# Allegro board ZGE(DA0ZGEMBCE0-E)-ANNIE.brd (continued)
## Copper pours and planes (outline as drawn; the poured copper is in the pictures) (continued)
S2 on TOP (solid shape): 249.07,33.95 249.07,32.25 249.12,32.2 249.12,31.97 249.09,31.97 249.09,31.26 249.09,31.23 248.91,31.23 248.89,31.26 248.89,31.26 248.89,31.97 248.86,31.97 248.86,32.05 248.74,32.17 245.54,32.17 245.43,32.27 245.43,32.43 245.49,32.48 245.49,32.47 246.2,32.47 246.2,32.5 246.37,32.5 246.42,32.55 246.42,33.77 246.35,33.85 246.2,33.85 246.2,33.87 245.49,33.87 245.46,33.9 245.46,34.05 245.49,34.08 245.49,34.07 246.2,34.07 246.2,34.1 248.91,34.1
S2 on BOTTOM (solid shape): 249.07,33.95 249.07,32.33 248.91,32.17 246.55,32.17 246.42,32.3 246.42,33.95 246.58,34.1 248.91,34.1
S_SPKR+ on TOP (solid shape): 20.82,19.4 20.82,18.13 20.67,17.97 19.98,17.97 19.5,17.49 19.5,16.58 18.86,15.94 16.53,15.94 16.35,16.12 16.35,16.73 16.66,17.03 17.35,17.03 17.4,16.98 18.49,16.98 19.42,17.92 19.42,18.25 19.54,18.37 19.54,19.26 19.75,19.47 20.75,19.47
S_SPKR- on TOP (solid shape): 18.64,15.49 18.64,14.55 18.36,14.27 16.58,14.27 16.41,14.43 16.41,15.33 16.68,15.6 18.53,15.6
S_SPKR- on BOTTOM (solid shape): 20.14,19.47 20.14,15.08 19.91,14.85 19.24,14.85 18.5,14.11 17.58,14.11 17.25,14.44 17.25,15.89 17.88,16.52 18.32,16.52 19.07,17.26 19.07,17.28 19.08,17.3 19.17,17.38 19.17,19.57 19.19,19.61 19.22,19.63 19.98,19.63
TBTA_CC1 on TOP (solid shape): 291.8,41.81 292.68,41.81 292.71,41.8 292.73,41.76 292.73,41.54 291.8,41.54 291.8,41.51 291.71,41.42 291.28,41.42 291.26,41.41 291.11,41.31 291.01,41.16 291.01,41.15 290.72,40.85 290.36,40.85 290.33,40.86 290.3,40.87 290.22,40.87 290.18,40.91 290.01,40.91 289.34,40.91 289.25,41 289.22,41.03 289.19,41.07 289.17,41.1 289.17,41.44 289.28,41.55 289.66,41.55 289.68,41.54 289.69,41.52 289.82,41.37 290.01,41.32 290.18,41.36 290.31,41.48 290.32,41.49 290.37,41.52 290.43,41.49 290.54,41.46 290.64,41.45 290.98,41.56 291.19,41.85 291.19,41.86 291.22,41.88 291.65,41.88 291.67,41.9 291.8,41.9
TBTA_CC2 on TOP (solid shape): 290.92,46.27 290.92,45.66 290.91,45.61 290.91,45.52 290.9,45.51 290.8,45.41 290.44,45.41 290.32,45.53 290.32,45.76 290.15,45.93 289.72,45.93 289.38,45.58 289.07,45.58 288.92,45.74 288.92,46.07 289.36,46.51 290.68,46.51
TBTA_VBUS_L on TOP (solid shape): 253.36,31.77 253.37,31.74 253.35,31.67 253.35,31.61 253.36,31.5 253.41,31.4 253.41,30.67 253.16,30.42 252.22,30.42 252.01,30.62 252.01,30.8 251.66,31.16 251.38,31.16 251.29,31.24 251.29,31.98 251.31,32.02 251.34,32.03 252.91,32.03 252.95,32.07 253.05,32.07
TBTA_VBUS_L on BOTTOM (solid shape): 287.17,48.99 287.17,47.11 286.78,46.73 283.43,46.73 283.3,46.85 283.3,48.81 283.81,49.32 286.84,49.32
TBTA_VBUS_L on IN2 (solid shape): outline of 1577 points within 284.4,39.47 294.23,48.63
TBTA_VBUS_L on SVCC1 (solid shape): outline of 800 points within 251.28,27.98 295.42,50.08
TPM_VDD on BOTTOM (solid shape): 242.54,19.17 242.89,19.17 243,19.07 243,18.38 242.87,18.25 241.96,18.25 241.74,18.03 241.24,18.03 241.14,17.92 241.13,17.88 241.09,17.87 241.08,17.87 241.08,16.87 241.04,16.83 240.82,16.83 240.79,16.85 240.77,16.88 240.77,17.87 240.76,17.87 240.72,17.88 240.71,17.92 240.71,18.23 240.89,18.41 240.9,18.41 240.95,18.44 240.97,18.48 240.98,18.5 241.01,18.53 241.01,18.79 241.34,19.12 241.75,19.12 241.98,19.35 242.36,19.35
TPM_VDD on BOTTOM (solid shape): 234.24,15.85 234.27,15.85 234.29,15.83 234.63,15.62 234.98,15.83 235,15.85 235.02,15.85 235.26,15.85 236.38,14.73 236.41,14.66 236.39,14.59 236.3,14.46 236.28,14.32 236.39,14.04 236.67,13.92 236.73,13.93 236.81,13.9 236.85,13.83 236.85,12.84 237,12.69 238.52,12.69 238.58,12.64 238.58,11.68 238.6,11.66 238.6,11.6 238.83,11.37 239.57,11.37 239.74,11.19 239.74,10.53 239.57,10.35 237.99,10.35 237.36,9.72 236.24,9.72 236.19,9.77 236.19,11.83 235.3,12.72 235.3,13.28 233.59,14.98 233.59,15.03 233.56,15.18 233.47,15.31 233.47,15.62 233.7,15.85
TPM_VDD on IN1 (solid shape): outline of 116 points within 233.37,14.88 242.52,18.65
USB3_RT_0V9 on TOP (solid shape): 270.42,36.05 270.42,36.03 270.46,35.9 270.55,35.78 270.55,35.76 270.55,34.89 270.44,34.77 270.42,34.77 270.24,34.67 270.14,34.49 270.14,34.47 269.92,34.26 269.92,33.97 269.89,33.88 269.88,33.8 269.89,33.72 269.92,33.63 269.92,33.52 269.79,33.39 268.95,33.39 268.88,33.47 268.88,36.08 269.06,36.26 270.2,36.26
USB3_RT_0V9 on TOP (solid shape): 269.53,30.49 269.53,28.41 269.52,28.38 269.48,28.36 268.76,28.36 268.5,28.52 268.2,28.57 268.12,28.57 268.04,28.56 268.02,28.56 268,28.56 267.9,28.61 267.79,28.63 267.67,28.61 267.57,28.56 267.55,28.56 267.53,28.56 267.44,28.57 267.35,28.57 267.1,28.53 266.87,28.42 266.86,28.41 266.82,28.41 266.74,28.49 266.74,29.4 266.85,29.51 267.68,29.51 267.99,29.81 267.99,30.6 268.16,30.77 268.17,30.77 268.28,30.81 268.37,30.88 269.14,30.88
USB3_RT_0V9 on BOTTOM (solid shape): 269.44,30.83 269.44,29.86 269.21,29.63 267.68,29.63 267.58,29.73 267.58,30.35 267.99,30.76 268.02,30.77 268.09,30.76 268.27,30.81 268.43,30.95 268.46,30.95 269.31,30.95
USB3_RT_0V9 on BOTTOM (solid shape): 270.42,36.22 270.43,36.19 270.42,36.13 270.41,36.08 270.45,35.93 270.55,35.78 270.55,35.76 270.55,34.89 270.48,34.82 270.46,34.81 270.33,34.78 270.23,34.71 269.03,34.71 268.88,34.87 268.88,36.14 269.08,36.34 270.3,36.34
USB3_RT_0V9 on IN4 (solid shape): outline of 608 points within 261.89,30.39 270.73,37
USB3_RT_DCDC_GND on TOP (solid shape): 268.88,38.29 268.88,37.91 268.83,37.86 265.68,37.86 265.58,37.96 265.58,38.29 265.8,38.52 268.65,38.52
USB3_RT_DCDC_GND on BOTTOM (solid shape): 265.33,34.83 265.33,34.57 265.65,34.26 265.65,33.93 265.55,33.82 265.19,33.82 264.94,34.08 263.85,34.08 263.75,34.18 263.75,34.94 263.87,35.07 265.09,35.07
USB3_RT_DCDC_GND on BOTTOM (solid shape): 268.88,38.29 268.88,36.85 268.37,36.34 268.37,34.61 268.22,34.46 268.01,34.46 267.8,34.67 267.8,34.8 267.61,34.99 267.61,36.08 267.91,36.39 267.91,37.05 267.63,37.33 266.74,37.33 266.41,37 265.68,37 265.58,37.1 265.58,38.29 265.8,38.52 268.65,38.52
USB3_RT_DCDC_GND on SGND (solid shape): 268.88,38.29 268.88,36.85 268.44,36.42 268.39,36.33 268.37,36.24 268.37,34.18 267.63,33.44 266.7,33.44 266.26,33.88 266.18,33.93 266.08,33.95 265.95,33.91 265.86,33.81 265.21,33.81 264.98,34.04 264.95,34.06 264.92,34.07 263.78,34.07 263.73,34.11 263.73,34.98 263.83,35.08 264.76,35.08 264.8,35.09 264.83,35.11 265.32,35.6 265.5,35.68 265.58,35.86 265.58,38.29 265.81,38.52 268.65,38.52
USB3_RT_DCDC_GND on IN1 (solid shape): outline of 95 points within 263.75,33.44 268.88,38.52
USB3_RT_DCDC_GND on SGND3 (solid shape): 268.88,38.29 268.88,36.85 268.44,36.42 268.39,36.33 268.37,36.24 268.37,34.18 267.63,33.44 266.7,33.44 266.26,33.88 266.18,33.93 266.08,33.95 265.95,33.91 265.86,33.81 265.21,33.81 264.98,34.04 264.95,34.06 264.92,34.07 263.78,34.07 263.73,34.11 263.73,34.98 263.83,35.08 264.76,35.08 264.8,35.09 264.83,35.11 265.32,35.6 265.5,35.68 265.58,35.86 265.58,38.29 265.81,38.52 268.65,38.52
USB3_RT_VIN on TOP (solid shape): 268.88,37.58 268.88,37 268.7,36.82 267.89,36.82 267.53,36.47 266.77,36.47 266.36,36.06 266.36,35.65 265.55,34.84 264.76,34.84 264.73,34.87 263.8,34.87 263.76,34.88 263.75,34.92 263.75,34.99 263.82,35.07 264.81,35.07 265.32,35.58 265.42,35.58 265.58,35.73 265.58,37.51 265.78,37.71 268.75,37.71
USB3_RT_VIN on BOTTOM (solid shape): 267.73,36.92 267.73,36.44 267.43,36.14 267.43,34.97 267.66,34.74 267.66,33.57 267.56,33.47 266.69,33.47 265.6,34.56 265.6,36.57 265.86,36.82 266.44,36.82 266.74,37.13 267.53,37.13
USB3_RT_VX on TOP (solid shape): 267.73,36.14 267.73,34.84 267.72,34.74 267.73,34.64 267.73,33.54 267.63,33.44 266.69,33.44 266.19,33.95 265.88,33.95 265.61,34.22 265.61,34.23 265.55,34.3 265.47,34.36 265.47,34.37 265.42,34.41 265.28,34.41 264.79,34.41 264.75,34.42 264.73,34.46 264.73,34.47 263.77,34.47 263.74,34.48 263.72,34.52 263.72,34.62 263.74,34.66 263.77,34.67 264.73,34.67 264.73,34.68 264.76,34.71 265.7,34.71 266.57,35.58 266.57,35.93 266.85,36.21 267.66,36.21
USB3O2_MUX_AVDD33 on TOP (solid shape): 277.8,30.88 277.83,30.87 278.15,30.53 278.58,30.41 278.81,30.41 278.95,30.27 279.49,30.27 279.53,30.26 279.55,30.22 279.55,28.92 279.52,28.9 279.52,27.96 279.04,27.47 278.02,27.47 277.67,27.83 277.67,28.56 277.68,28.59 277.94,28.74 278.04,29 277.99,29.18 277.86,29.34 277.85,29.36 277.85,29.57 277.67,29.75 277.67,29.76 277.58,29.85 277.58,29.85 277.58,30.84 277.62,30.88
USB3O2_MUX_AVDD33 on IN4 (solid shape): 278.76,30.53 278.76,29.4 278.45,29.1 277.87,29.1 276.93,30.04 271.82,30.04 271.62,30.24 271.62,31.03 271.94,31.35 277.95,31.35
USB_CC1 on TOP (solid shape): 286.6,36.82 287.73,36.82 288.23,36.31 288.23,35.98 288.16,35.91 287.74,35.91 287.59,36.06 287.59,36.07 287.55,36.16 287.46,36.2 287.12,36.19 286.61,36.19 286.47,36.06 286.31,36.06 286.19,36.18 285.95,36.18 285.95,36.19 285.95,36.67 286.12,36.85 286.58,36.85
USB_CC2 on TOP (solid shape): 286.53,38.68 286.54,38.66 286.54,38.64 286.52,38.56 286.52,38.5 286.55,38.34 286.64,38.21 286.66,38.17 286.66,37.86 286.96,37.56 287,37.56 287.05,37.52 287.11,37.5 287.14,37.49 287.18,37.49 287.26,37.48 287.29,37.47 287.66,37.47 287.74,37.56 288.16,37.56 288.61,37.1 288.61,36.8 288.49,36.67 288.18,36.67 287.92,36.94 287.84,36.94 287.83,36.95 286.66,36.95 285.95,37.66 285.95,38.04 285.69,38.29 285.69,38.57 285.97,38.85 286.35,38.85
USBC_VBUS on TOP (solid shape): 108.67,144.04 109.29,144.04 109.57,144.31 112.85,144.31 113.14,144.03 113.14,141.4 112.25,140.5 108.13,140.5 107.57,139.95 105.75,139.95 105.67,140.02 105.67,140.55 106.05,140.93 106.05,142.17 105.23,142.99 105.23,144.44 105.35,144.57 108.14,144.57
USBC_VBUS on BOTTOM (solid shape): outline of 230 points within 285.16,34.99 291.05,39.53
USBC_VBUS on SVCC (solid shape): outline of 2341 points within 110.51,24.45 294.28,156.02
USBC_VBUS on IN3 (solid shape): outline of 1380 points within 287.27,24.5 297.2,38.32
VA on TOP (solid shape): 120.26,167.53 120.26,166.67 120.87,166.06 122.24,166.06 123.21,167.02 123.21,167.91 123.39,168.09 125.49,168.09 125.82,167.76 125.82,166.49 125.32,165.98 125.32,163.72 125.72,163.31 126.61,163.31 127.45,162.47 127.45,159.38 126.87,158.79 126.87,158 126.74,157.88 125.98,157.88 124.89,158.97 121.18,158.97 120.9,158.69 120.9,157.98 120.54,157.62 119.96,157.62 119.73,157.85 119.73,163.26 119.28,163.71 117.93,163.71 117.47,164.16 117.47,167.83 117.85,168.22 119.58,168.22
VA on BOTTOM (solid shape): 95.41,52.61 95.41,52.47 95.41,52.41 95.44,52.35 95.45,52.33 95.45,51.65 95.27,51.48 95.04,51.48 94.86,51.65 94.86,51.81 94.61,52.06 94.3,52.06 94.1,52.26 94.1,52.75 94.2,52.85 95.17,52.85
VA on BOTTOM (solid shape): 119.98,167.63 119.98,166.46 120.54,165.9 122.52,165.9 123.18,166.56 123.18,167.68 123.64,168.14 125.39,168.14 125.8,167.73 125.8,162.81 125.72,162.73 118.51,162.73 117.27,163.97 117.27,167.55 117.85,168.14 119.47,168.14
N18847325 on TOP (solid shape): 167.13,160.54 167.13,159.1 168.55,157.67 168.55,153.36 168.07,152.87 166.08,152.87 165.78,153.18 165.78,153.52 165.74,153.62 165.64,153.66 165.26,153.66 165.16,153.62 165.12,153.52 165.12,153.18 165.12,153.14 165.14,153.1 165.14,152.21 164.69,151.76 161.18,151.76 160.55,152.39 160.55,155.46 161.05,155.97 162.15,155.97 162.55,156.38 162.55,159.2 162.68,159.33 166.21,159.33 166.41,159.53 166.41,160.47 166.62,160.67 167,160.67
N18847325 on BOTTOM (solid shape): 167.56,158.36 167.56,156.4 167.48,156.33 166.52,156.33 166.31,156.53 166.31,158.36 166.54,158.59 167.33,158.59
N18869846 on BOTTOM (solid shape): 165.75,158.11 165.75,156.46 165.68,156.38 165.04,156.38 164.89,156.53 164.89,158.13 165.09,158.33 165.53,158.33
N18875415 on TOP (solid shape): 156.53,160.42 156.53,159.3 156.97,158.86 156.97,156.27 158.13,155.11 158.13,152.57 157.7,152.14 155.29,152.14 155.09,152.34 155.09,153.64 154.98,153.74 154.37,153.74 154.27,153.64 154.27,151.98 153.89,151.6 149.83,151.6 149.29,152.14 149.29,155.97 149.42,156.1 151.43,156.1 151.71,156.38 151.71,158.94 151.96,159.2 155.37,159.2 155.8,159.63 155.8,160.62 155.9,160.72 156.23,160.72
N18875415 on BOTTOM (solid shape): 156.71,158.28 156.71,156.63 156.58,156.51 155.72,156.51 155.44,156.79 155.44,158.36 155.59,158.51 156.48,158.51
N18875619 on BOTTOM (solid shape): 154.98,158.39 154.98,156.61 154.86,156.48 154.43,156.48 154.17,156.73 154.17,158.36 154.37,158.56 154.81,158.56
N18877670 on TOP (solid shape): 146.6,160.6 146.6,153.18 145.66,152.24 144.39,152.24 143.91,152.72 143.91,153.41 143.68,153.64 143.63,153.64 143.59,153.64 143.21,153.64 143.18,153.64 143.02,153.64 142.94,153.56 142.94,152.37 142.79,152.21 139.21,152.21 138.58,152.85 138.58,155.77 138.96,156.15 140.71,156.15 141.24,156.68 141.24,159.05 141.55,159.35 145.61,159.35 145.76,159.5 145.76,160.8 145.81,160.85 146.35,160.85
N18877670 on BOTTOM (solid shape): 146.12,158.33 146.12,156.76 145.99,156.63 145.18,156.63 144.98,156.84 144.98,158.33 145.21,158.56 145.89,158.56
N18877832 on BOTTOM (solid shape): 144.44,158.46 144.44,156.71 144.34,156.61 143.73,156.61 143.5,156.84 143.5,158.39 143.78,158.66 144.24,158.66
N18879722 on TOP (solid shape): 136.06,160.57 136.06,158.66 135.76,158.36 135.76,153.1 135.22,152.57 133.09,152.57 132.63,153.03 132.63,153.61 132.56,153.69 132,153.69 131.95,153.64 131.95,152.82 131.67,152.54 128.77,152.54 128.03,153.28 128.03,156.02 128.49,156.48 129.71,156.48 130.14,156.91 130.14,157.93 131.44,159.22 135.07,159.22 135.27,159.43 135.27,160.65 135.32,160.7 135.93,160.7
N18879722 on BOTTOM (solid shape): 135.32,158.18 135.32,156.86 135.22,156.76 134.44,156.76 134.28,156.91 134.28,158.11 134.51,158.33 135.17,158.33
N18879884 on BOTTOM (solid shape): 133.78,158.51 133.78,156.84 133.65,156.71 133.06,156.71 132.86,156.91 132.86,158.41 133.11,158.66 133.62,158.66
N18886117 on TOP (solid shape): 124.35,156.33 124.78,156.33 125.34,155.77 125.34,152.87 124.76,152.29 123.49,152.29 123.36,152.42 123.36,153.97 123.23,154.09 123.13,154.09 123.09,154.1 122.71,154.1 122.68,154.09 122.62,154.09 122.42,153.89 122.42,152.39 119.63,149.6 118.2,149.6 118.13,149.67 118.13,153.38 117.85,153.66 116.76,153.66 116.6,153.81 116.6,154.42 118,155.82 119.32,155.82 120.26,156.76 123.92,156.76
N18886117 on BOTTOM (solid shape): 120.01,154.42 120.01,153.03 119.93,152.95 119.32,152.95 119.22,153.05 119.22,154.42 119.35,154.55 119.88,154.55
N18886423 on BOTTOM (solid shape): 118.64,153.69 118.64,151.98 118.46,151.81 118,151.81 117.87,151.93 117.87,153.74 117.95,153.81 118.51,153.81
N19453152 on TOP (solid shape): 199.78,48.29 199.78,48.1 201.16,46.72 201.16,46.27 202.78,44.65 203.7,44.65 203.78,44.57 203.78,44.02 203.77,43.98 203.73,43.97 203.62,43.86 203.45,43.86 203.33,43.98 202.5,43.98 201.18,45.3 199.59,45.3 199.46,45.43 199.46,46.02 199.15,46.33 199.15,47.06 199.01,47.2 199.01,47.21 199.01,48.29 199.1,48.38 199.69,48.38
N20974305 on TOP (solid shape): 96.53,78.49 96.53,77.91 96.21,77.59 96.11,77.59 96.06,77.55 96.05,77.54 95.82,77.41 95.73,77.16 95.85,76.88 96.13,76.76 96.24,76.78 96.34,76.82 96.37,76.83 96.4,76.81 96.44,76.78 96.44,75.91 96.37,75.79 96.35,75.66 96.46,75.38 96.73,75.26 96.76,75.26 97,75.02 97,74.59 96.97,74.51 96.97,74.44 96.97,74.37 97,74.3 97,73.63 96.89,73.52 96.41,73.52 96.28,73.65 96.28,74.74 96.12,74.91 96.11,74.92 96.08,74.98 96.02,75.02 96.01,75.02 95.17,75.86 95.17,77.55 95.18,77.58 95.38,77.58 95.48,77.62 95.52,77.72 95.52,78.33 95.78,78.58 96.44,78.58
N21715610 on BOTTOM (solid shape): 74.54,29.22 74.65,29.19 74.76,29.18 74.83,29.2 74.9,29.23 77.25,29.23 77.32,29.2 77.35,29.12 77.35,29.12 77.46,28.84 77.74,28.73 77.79,28.73 77.87,28.74 77.89,28.72 78,28.62 78,28.33 78,27.01 77.99,27 77.86,27 77.82,27.01 77.81,27.05 77.81,27.72 77.61,27.72 77.61,27.05 77.59,27.01 77.56,27 77.2,27 76.93,27.27 76.93,27.55 76.7,27.78 74.97,27.78 74.72,27.52 74.72,27.2 74.71,27.16 74.47,27.01 74.38,26.76 74.44,26.56 74.59,26.42 74.64,26.34 74.61,26.25 74.5,26.12 74.47,25.95 74.5,25.78 74.61,25.65 74.65,25.57 74.62,25.49 74.08,24.95 73.35,24.95 73.17,25.13 73.17,26.43 73.2,26.51 73.28,26.54 73.3,26.53 73.58,26.65 73.69,26.93 73.59,27.19 73.34,27.32 73.2,27.35 73.17,27.42 73.17,28.77 73.63,29.23 74.53,29.23
N21715657 on BOTTOM (solid shape): outline of 266 points within 79.41,25.37 84.37,30.32
N21716560 on TOP (solid shape): 95.93,30.12 95.93,29.3 95.8,29.18 94.05,29.18 93.74,28.87 93.74,27.3 94.14,26.9 94.14,26.72 94.12,26.68 94.09,26.67 93.42,26.67 93.42,26.45 94.12,26.45 94.13,26.44 94.14,26.42 94.14,26.32 94.12,26.28 94.09,26.27 93.25,26.27 92.81,26.71 92.53,26.71 92.2,27.03 92.2,28.59 92.23,28.64 92.24,28.65 92.46,29 92.24,29.35 92.23,29.36 92.2,29.4 92.2,30.12 92.3,30.22 95.83,30.22
N21716605 on TOP (solid shape): 93.42,24.85 94.16,24.85 94.16,24.72 94.15,24.68 94.11,24.67 93.42,24.67 93.42,24.45 94.16,24.45 94.16,24.23 93.97,24.04 93.67,24.04 93.4,23.78 93.4,22.53 93.59,22.34 93.65,22.34 93.74,22.31 93.82,22.3 93.9,22.31 93.99,22.34 94.02,22.34 94.08,22.4 94.15,22.43 94.22,22.4 94.34,22.33 94.48,22.3 94.72,22.38 94.86,22.59 94.87,22.62 95.52,22.62 95.62,22.52 95.62,21.73 94.97,21.08 93.83,21.08 93.83,21.09 93.54,21.09 93.54,21.23 93.49,21.33 93.4,21.37 93.02,21.37 93,21.4 92.28,21.4 91.94,21.73 91.94,22.15 91.99,22.26 92.01,22.38 91.99,22.48 91.96,22.56 91.94,22.58 91.94,22.77 92.25,23.08 92.25,24.76 92.4,24.91 93.42,24.91
N23334321 on TOP (solid shape): 160.57,25.26 160.57,24.98 160.47,24.88 159.91,24.88 159.78,24.76 159.78,24.27 159.73,24.22 159.15,24.22 159.02,24.35 158.67,24.35 158.57,24.45 158.57,24.71 159.18,25.31 160.52,25.31
N25255301 on TOP (solid shape): 119.47,163.19 119.47,160.06 119.3,159.88 118.41,159.88 117.87,159.35 117.87,158.94 117.39,158.46 117.39,157.42 117.21,157.24 116.4,157.24 116.3,157.34 116.3,158.21 116.66,158.56 116.66,162.07 116.99,162.4 117.47,162.4 117.75,162.68 117.75,163.19 118.13,163.57 119.09,163.57
N25255306 on TOP (solid shape): 72.66,47.75 72.66,45.05 71.79,44.17 68.03,44.17 68.01,44.19 64.96,44.19 64.78,44.37 64.78,44.74 64.84,44.79 64.99,44.94 64.99,45.26 64.05,46.19 63.8,46.19 63.59,46.4 63.59,46.63 63.72,46.75 64.5,46.75 64.81,47.07 66.49,47.07 66.49,47.02 66.53,46.92 66.63,46.88 67.01,46.88 67.11,46.92 67.15,47.02 67.15,47.08 67.39,47.32 67.41,47.31 67.55,47.34 67.67,47.41 68.95,47.41 69.7,48.17 72.25,48.17
N25255314 on TOP (solid shape): 119.5,159.4 119.5,157.52 119.12,157.14 117.82,157.14 117.62,157.34 117.62,158.39 118.05,158.82 118.05,159.3 118.43,159.68 119.22,159.68
N25255423 on TOP (solid shape): 116.06,163.52 116.06,158.83 114.52,157.29 106.52,157.29 106.37,157.45 106.37,160.14 106.65,160.42 110.79,160.42 111.07,160.7 111.07,163.11 111.58,163.63 115.95,163.63
N33880211 on TOP (solid shape): 226.84,24.52 226.91,24.49 226.96,24.44 226.96,24.41 227.08,24.29 227.22,24.29 227.74,24.29 228.72,23.3 228.72,22.36 230.35,20.73 230.35,19.77 230.88,19.24 231.49,19.24 231.63,19.11 231.63,19.09 231.64,19.02 231.67,18.95 231.67,18.56 231.66,18.55 230.76,18.55 230.69,18.48 230.3,18.48 230.21,18.57 230.21,18.91 230.13,18.99 230.12,19 230.03,19.17 229.86,19.27 229.85,19.27 229.66,19.46 229.66,19.71 229.66,20.2 229.58,20.29 229.55,20.31 229.34,20.52 229.3,20.52 229.27,20.55 227.73,22.08 227.73,22.72 227.75,22.76 227.76,22.77 227.86,23.02 227.76,23.27 227.75,23.28 227.73,23.32 227.73,23.43 227.61,23.56 227.61,23.56 227.35,23.82 226.99,23.82 226.89,23.92 226.87,23.92 226.62,24.17 226.62,24.35 226.71,24.44 226.77,24.49
N36119386 on TOP (solid shape): 106.88,96.99 106.94,96.99 107.1,96.83 107.1,96.81 107.08,96.72 107.07,96.65 107.19,96.37 107.47,96.26 107.68,96.26 107.78,96.16 108.93,96.16 109.05,96.05 109.05,95.58 108.87,95.41 107.6,95.41 107.58,95.42 107.57,95.44 107.42,95.59 107.22,95.65 107.06,95.61 106.93,95.52 106.86,95.48 106.78,95.51 106.39,95.9 105.53,95.9 105.3,96.13 105.3,97.32 105.48,97.5 106.37,97.5
N37522596 on TOP (solid shape): 234.6,57.47 234.6,57.46 235.4,57.46 235.44,57.44 235.45,57.41 235.45,57.23 235.44,57.19 235.4,57.18 234.6,57.18 234.6,57.17 234.57,57.14 234.46,57.14 234.08,56.76 234.08,56.67 233.94,56.53 233.94,55.37 234.08,55.23 234.08,54.55 233.68,54.15 229.65,54.15 229.13,54.68 229.13,56.84 229.79,57.5 234.57,57.5
N37522596 on BOTTOM (solid shape): 233.43,60.03 233.43,58.26 233.83,57.86 233.83,55.08 233.62,54.88 230.27,54.88 229.79,55.36 229.79,59.81 230.22,60.24 233.22,60.24
N37551639 on BOTTOM (solid shape): 228.59,59.88 228.59,58.26 228.26,57.93 227.58,57.93 227.53,57.94 227.49,57.94 227.44,57.94 227.39,57.93 225.39,57.93 225.27,58.06 225.27,58.72 225.34,58.78 225.77,58.78 226.16,59.18 226.16,60.1 226.26,60.19 228.29,60.19
N53212830 on TOP (solid shape): 36.87,35.31 36.87,34.85 36.87,34.83 36.77,34.69 36.75,34.54 36.75,33.95 36.75,33.89 36.77,33.82 36.77,33.7 36.62,33.56 36.15,33.56 36.06,33.65 34.46,33.65 34.42,33.67 34.38,33.72 34.33,33.76 34.32,33.78 34.31,33.8 34.31,34 34.39,34.08 34.42,34.09 34.45,34.09 34.83,34.09 34.86,34.09 34.9,34.11 35.79,34.11 36.32,34.63 36.32,35.35 36.39,35.41 36.77,35.41
N53212904 on TOP (solid shape): 31.79,36.29 31.79,36.04 31.77,35.97 31.7,35.94 31.33,35.57 31.66,35.16 31.67,35.16 31.72,35.11 31.72,34.84 31.62,34.74 30.98,34.74 30.78,34.54 30.78,34.15 30.51,33.88 30.51,32.87 30.47,32.83 30.34,32.83 30.31,32.87 30.31,33.97 30.32,33.99 30.33,34.01 30.5,34.28 30.39,34.58 30.38,34.59 30.37,34.61 30.37,35.25 31.11,35.98 31.11,36.29 31.24,36.41 31.67,36.41
N53217580 on TOP (solid shape): 12.14,22.77 12.14,22.5 11.97,22.33 11.96,22.31 11.38,21.74 11.18,21.74 10.53,21.09 10.53,20.36 10.3,20.12 9.62,20.12 9.6,20.13 9.58,20.14 9.54,20.18 9.54,21.08 9.52,21.1 9.51,21.12 9.5,21.14 9.5,21.22 9.58,21.3 10.19,21.3 10.76,21.87 10.76,22.19 10.99,22.41 10.99,22.66 11.12,22.79 12.12,22.79
N53217584 on TOP (solid shape): 10.46,26.76 10.46,26.41 11.47,25.39 11.96,25.39 12.16,25.19 12.16,24.83 12.12,24.79 11.13,24.79 11.13,24.78 11.04,24.78 10.71,25.11 10.71,25.37 10.28,25.8 9.47,25.8 9.26,26 9.26,26.99 9.37,27.09 10.13,27.09
N53218545 on TOP (solid shape): 22.35,17.62 22.35,16.62 22.26,16.53 20.15,16.53 20.03,16.65 20.03,17.41 20.34,17.72 22.24,17.72
N53218614 on TOP (solid shape): 24.62,16.11 24.65,16.03 24.61,15.95 24.25,15.13 24.82,14.44 24.82,14.09 24.69,13.96 23.26,13.96 23.13,14.08 23.13,15 23.24,15.11 23.33,15.11 23.34,15.1 23.43,15.07 23.53,15.05 23.81,15.17 23.93,15.45 23.92,15.52 23.9,15.6 23.9,16.13 23.9,16.27 23.9,16.27 24.45,16.27
N53276765 on TOP (solid shape): 42.97,104.97 43,104.96 43.02,104.94 43.08,104.86 43.16,104.81 43.17,104.81 43.71,104.27 43.71,104.26 43.77,104.17 43.86,104.11 43.87,104.11 44.13,103.85 44.13,102.81 44.11,102.77 44.07,102.76 43.2,102.76 43.07,102.89 43.07,103.01 43.55,103.5 43.55,103.75 43.33,103.98 42.64,103.98 42.32,104.3 42.32,104.5 42.44,104.61 42.72,104.61 42.92,104.82 42.92,104.94 42.95,104.97
N53276791 on TOP (solid shape): 45.07,107.9 45.08,107.88 45.08,107.86 45.08,107.14 45.04,107.06 44.95,107.05 44.89,107.06 44.84,107.06 44.53,106.76 44.84,106.45 44.89,106.46 44.95,106.47 45.04,106.46 45.08,106.38 45.08,105.57 45.08,105.55 45.07,105.54 44.74,105.21 44.33,105.21 44.01,104.9 43.91,104.9 43.52,105.29 43.52,105.92 43.41,106.03 43.09,106.03 42.95,105.89 42.44,105.89 42.36,105.81 42.18,105.81 42.08,105.91 42.08,106.29 43.93,108.14 44.82,108.14
N53276791 on BOTTOM (solid shape): 42.18,106.96 43,106.96 43.1,106.86 43.1,106.03 42.99,105.92 42.59,105.92 42.48,105.81 42.35,105.81 42.35,105.81 42.06,105.81 41.88,105.99 41.88,106.36 41.47,106.77 41.47,107.14 41.54,107.21 41.93,107.21
N53369186 on TOP (solid shape): 279.03,38.75 279.7,38.75 279.8,38.65 279.8,38.3 279.78,38.26 279.75,38.25 277.4,38.25 276.56,37.4 276.56,36.54 276.56,36.48 276.58,36.42 276.58,36.06 276.57,36.02 276.53,36.01 276.43,36.01 276.4,36.02 276.38,36.06 276.38,37.04 276.37,37.04 276.34,37.05 276.32,37.08 276.29,37.13 276.29,37.91 276.52,38.13 276.54,38.13 276.7,38.21 276.76,38.37 276.76,38.63 276.93,38.8 278.97,38.8
N53369186 on BOTTOM (solid shape): 277.72,37.81 277.72,37.13 277.59,37 276.17,37 275.84,37.33 275.84,38.45 276.07,38.68 276.85,38.68
N53638085 on TOP (solid shape): 19.04,19.42 19.04,18.08 18.33,17.36 17.56,17.36 17.28,17.64 17.28,18.26 17.12,18.42 17.12,19.16 17.49,19.52 18.94,19.52
N53638085 on BOTTOM (solid shape): 18.79,19.52 18.79,17.54 18.56,17.31 17.29,17.31 17.14,17.47 17.14,18.81 17.95,19.63 18.69,19.63
N53716068 on TOP (solid shape): 216.68,61.18 217.2,61.09 217.32,60.98 217.32,59.71 217.19,59.58 215.11,59.58 214.62,60.06 214.62,60.98 214.93,61.28 216.17,61.28
N56085154 on BOTTOM (solid shape): 98.95,164.9 98.95,164.2 98.97,164.14 99.01,164.09 99.01,164.04 99.44,163.6 99.44,162.23 99.32,162.1 97.32,162.1 97.23,162.14 97.12,162.16 97.03,162.15 96.94,162.11 96.92,162.1 96.89,162.11 96.82,162.17 96.81,162.19 96.81,162.21 96.83,162.29 96.83,162.35 96.78,162.53 96.65,162.68 96.63,162.72 96.63,163.91 96.96,164.23 96.96,164.66 97.03,164.73 97.53,164.73 97.86,165.06 98.8,165.06
N56085203 on BOTTOM (solid shape): 100.27,160.93 100.27,159.87 100.06,159.66 99.51,159.66 99.36,159.5 99.36,158.44 99.29,158.36 99.29,157.67 99.11,157.49 98.38,157.49 98.25,157.62 98.25,158.31 98.24,158.36 98.24,158.84 98.62,159.22 98.62,160.37 98.85,160.6 98.88,160.63 98.91,160.67 98.93,160.69 98.95,160.7 98.99,160.7 99.3,161.01 100.2,161.01
N56197477 on TOP (solid shape): 47.64,19.63 47.64,19.24 48.43,18.46 48.91,18.46 49.09,18.28 49.09,18.1 48.98,17.98 47.28,17.98 47.26,18 47.26,18.76 46.98,19.04 46.98,19.7 47.14,19.85 47.42,19.85
N56197477 on BOTTOM (solid shape): 47.54,20.06 47.54,19.35 48.1,18.79 48.1,18.13 47.92,17.95 47.34,17.95 47.24,18.05 47.24,18.43 46.37,19.29 46.37,20.18 46.48,20.29 47.31,20.29
N56482348 on TOP (solid shape): 48.08,28.14 48.08,27.6 47.66,27.18 47.29,27.18 46.59,26.49 45.93,26.49 45.93,26.5 44.95,26.5 44.92,26.52 44.92,26.74 44.94,26.75 46.31,26.75 46.81,27.25 46.81,27.59 47.11,27.9 47.11,28.17 47.22,28.28 47.95,28.28
N56482351 on TOP (solid shape): 45.41,28.71 45.41,27.8 45.95,27.26 45.95,26.97 45.94,26.95 44.91,26.95 44.89,26.98 44.89,27.61 44.52,27.98 44.52,28.68 44.53,28.71 44.58,28.76 45.35,28.76
N56482420 on TOP (solid shape): 47.08,25.14 48.02,25.14 48.18,24.98 48.18,24.07 48,23.89 47.22,23.89 45.97,25.14 45.93,25.14 45.93,25.15 44.94,25.15 44.91,25.17 44.91,25.38 44.94,25.4 46.47,25.4 46.47,25.41 46.81,25.41
N56482438 on TOP (solid shape): 47.29,23.59 47.92,23.59 48.08,23.44 48.08,22.57 47.9,22.39 46.53,22.39 45.94,22.98 45.64,22.98 44.93,23.69 44.93,24.93 44.95,24.95 45.92,24.95
N56545499 on TOP (solid shape): 11.13,23.24 12.1,23.24 12.14,23.23 12.16,23.19 12.16,23.04 12.14,23 12.1,22.99 11.13,22.99 11.13,22.98 11.1,22.95 10.88,22.95 10.38,22.46 10.38,21.74 10.24,21.6 9.64,21.6 9.47,21.76 9.47,22.67 9.9,23.1 10.55,23.1 10.71,23.27 11.11,23.27
N56545754 on TOP (solid shape): 10.41,25.39 10.41,25.19 10.97,24.63 11.1,24.63 11.13,24.6 11.13,24.59 12.11,24.59 12.15,24.58 12.16,24.54 12.16,24.39 12.15,24.35 12.11,24.34 11.13,24.34 11.13,24.33 11.1,24.3 10.84,24.3 10.56,24.58 10.34,24.58 9.59,24.58 9.39,24.78 9.39,25.49 9.52,25.62 10.18,25.62
N56546274 on TOP (solid shape): 26,17.5 26,16.54 25.94,16.48 24.49,16.48 24.35,16.62 24.35,17.61 24.37,17.64 25.87,17.64
N56546363 on TOP (solid shape): 22.8,17.6 22.8,16.31 22.28,15.79 20.69,15.79 20.68,15.78 20.4,15.78 20.01,15.38 20.01,14.9 19.88,14.77 19.2,14.77 19.04,14.93 19.04,15.51 19.81,16.27 21.63,16.27 21.79,16.42 22.36,16.42 22.55,16.61 22.55,17.59 22.57,17.61 22.79,17.61
N56849590 on TOP (solid shape): 55.26,36.33 55.26,35.98 55.02,35.74 54.35,35.74 53.78,35.16 53.78,34.57 53.31,34.1 52.65,34.1 52.58,34.04 52.56,34.02 52.54,33.99 52.34,33.8 51.17,33.8 51.1,33.87 51.1,34.36 51.28,34.54 51.91,34.54 53.66,36.29 53.66,36.29 53.76,36.39 55.21,36.39
N57000372 on TOP (solid shape): 32.1,26.69 32.11,26.66 32.11,25.66 32.12,25.65 32.12,25.2 32.12,25.15 32.12,25.13 32.11,25.11 32.05,25.06 32.01,25 31.54,24.53 31.54,22.67 32.1,22.11 34,22.11 34.08,22.04 34.08,21.1 33.95,20.97 30.4,20.97 30.27,21.1 30.27,24.43 31.26,25.42 31.67,25.42 31.82,25.57 31.84,25.63 31.86,25.65 31.89,25.66 31.91,25.66 31.91,26.66 31.92,26.7 31.96,26.71 32.04,26.71 32.07,26.72
N58457890 on TOP (solid shape): 22.16,93.08 22.16,93.03 22.23,92.86 22.4,92.79 22.7,92.79 22.73,92.79 22.78,92.8 22.81,92.8 22.88,92.73 22.88,92.25 22.47,91.84 21.96,91.84 21.67,92.13 21.66,92.15 21.53,92.37 21.28,92.46 21.2,92.45 21.18,92.46 21.04,92.6 21.04,93.37 21.87,93.37
N58459581 on BOTTOM (solid shape): 247.39,17.21 247.39,16.42 247.3,16.3 247.27,16.15 247.3,16 247.39,15.87 247.39,14.44 247.03,14.09 245.8,14.09 245.78,14.09 245.62,14.23 245.44,14.28 245.42,14.28 245.2,14.49 245.2,15.38 245.71,15.89 245.71,17.19 245.97,17.44 247.16,17.44
N62406391 on TOP (solid shape): 33.62,83.36 33.72,83.36 34.18,82.9 34.29,82.9 34.31,82.89 34.53,82.72 34.78,82.66 35.13,82.66 35.17,82.65 35.18,82.61 35.18,82.57 35.17,82.54 35.13,82.52 34.78,82.52 34.57,82.48 34.38,82.36 34,82.36 33.72,82.08 32.84,82.08 32.71,82.21 32.71,82.87 32.58,83 31.95,83 31.87,83.07 31.87,83.51 31.97,83.61 33.37,83.61

Small or netless copper shapes (teardrops, artwork), in the pictures only: 92 on TOP, 52 on BOTTOM, 3 on IN2, 175 on IN3

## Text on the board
Ref Des/Silkscreen Bottom: PCIe | PCIe/SATA | REV:E | MODEL:ZGE | DA0ZGEMBCE0 | 1 | 2
User.Comments: 24x28 | 28x49 | 35x68 | 24x75 | 35x83 | 39x98 | 30x32 | 20x33 | 171.8 | 295.1
Ref Des/Silkscreen Top: DA0ZGEMBCE0 REV:E | VL | TBT | MODEL:ZGE
TOP-L: {\Fgdt;n}\Ftxt;3.3
User.13: GND | ADOGND | +1.2VSUS | +VIN | +3VPCU | NVVDD | +3V_S5 | +5V_S5 | +3V | +VCC_SA | +VCC_CORE | +VIN_GPU_TOTAL | USBC_VBUS | +3V_SSD1
User.28: DP_USB_MXU_DCDC_GND | USB3_RT_DCDC_GND | ADOGND | GND
User.29: ADOGND | GND
User.30: ADOGND | GND
User.31: DP_USB_MXU_DCDC_GND | USB3_RT_DCDC_GND | ADOGND | GND
User.34: REV:A-3
User.38: ADOGND | GND | USB3_RT_DCDC_GND | DP_USB_MXU_DCDC_GND
User.39: ADOGND | GND
User.40: ADOGND | GND
User.41: ADOGND | GND | USB3_RT_DCDC_GND | DP_USB_MXU_DCDC_GND
User.42: +1.2VSUS | +3VPCU | +5V_S5 | USBC_VBUS | GND | ADOGND | NVVDD | +3V_S5 | +VCC_CORE | +3V | +VIN_GPU_TOTAL | +VIN | +VCC_SA | +3V_SSD1
User.43: +5V_S5_TYPEC | GND | ADOGND | +5V | +VIN_VGACORE | NVVDD | FBVDDQ_MEM | +VIN | +VCC_SA | +3V_SUS | +1.2VSUS | +VCC_CORE | +5VPCU | +1V_S5 | +3V_DEEP_SUS | TBTA_VBUS_L | +VIN_GPU_TOTAL
User.44: FBVDDQ_MEM | +3V_SUS | +1.2VSUS | +5V_S5_TYPEC | GND | ADOGND | +VIN_VGACORE | +5V | NVVDD | +5VPCU | +VCC_CORE | +1V_S5 | +3V_DEEP_SUS | TBTA_VBUS_L | +VIN_GPU_TOTAL | +VIN | +VCC_SA
User.45: 4 | 6 | 3 | 2 | 8 | 20 | 40 | 5 | Excess check:May 03 10:13:10 2019 | No Route Under Component:Jan 24 15:23:55 2019 | PadStack_Check:May 03 10:07:19 2019 | TP check:May 03 10:07:24 2019 | XY-Check acute:May 03 10:18:08 2019 | XY-Check cline width:Jan 24 15:17:19 2019 | XY-Create nettxt:Mar 27 16:57:39 2019 | XY-Create plane:May 03 08:51:51 2019 | XY-Cross plane-BOTTOM-SGND3:May 03 10:22:39 2019 | XY-Cross plane-IN1-SGND1:May 03 10:19:57 2019 | XY-Cross plane-IN1-SGND:May 03 10:20:08 2019 | XY-Cross plane-IN2-SGND1:May 03 10:20:48 2019 | XY-Cross plane-IN2-SVCC:May 03 10:20:22 2019 | XY-Cross plane-IN3-SGND1:Mar 09 13:34:49 2018 | XY-Cross plane-IN3-SGND2:May 03 10:21:06 2019 | XY-Cross plane-IN3-SVCC1:May 03 10:21:20 2019 | XY-Cross plane-IN4-SGND2:May 03 10:22:15 2019 | XY-Cross plane-IN4-SGND3:May 03 10:21:47 2019 | XY-Cross plane-IN5-SGND3:Mar 09 13:35:26 2018 | XY-Cross plane-TOP-SGND:May 03 10:19:36 2019 | XY-Dxf to pin check:May 03 10:09:27 2019 | XY-Etch cross-IN1-IN2:Mar 09 13:34:00 2018 | XY-Etch cross-IN4-IN5:Mar 09 13:35:04 2018 | XY-Etch ref-BOTTOM-SGND3:May 03 10:23:10 2019 | XY-Etch ref-IN1-SGND1:May 03 10:20:08 2019 | XY-Etch ref-IN1-SGND:May 03 10:20:22 2019 | XY-Etch ref-IN2-SGND1:May 03 10:21:06 2019 | XY-Etch ref-IN2-SVCC:May 03 10:20:48 2019 | XY-Etch ref-IN3-SGND1:Mar 09 13:35:04 2018 | XY-Etch ref-IN3-SGND2:May 03 10:21:19 2019 | XY-Etch ref-IN3-SVCC1:May 03 10:21:46 2019 | XY-Etch ref-IN4-SGND2:May 03 10:22:39 2019 | XY-Etch ref-IN4-SGND3:May 03 10:22:14 2019 | XY-Etch ref-IN5-SGND3:Mar 09 13:35:41 2018 | XY-Etch ref-TOP-SGND:May 03 10:19:56 2019 | XY-Excess check:May 03 10:13:10 2019 | XY-Mask check:Jan 24 15:24:46 2019 | XY-NO Route Under Component:Jan 24 15:23:55 2019 | XY-Outline check:Apr 30 11:20:06 2019 | XY-PadStack_Check:May 03 10:07:19 2019 | XY-Plane net check:May 03 10:11:41 2019 | XY-Prop check:May 03 10:19:06 2019 | XY-Symbol cross:Aug 23 20:46:01 2017 | XY-TP check:May 03 10:07:24 2019 | XY-shape min check:May 03 10:04:46 2019 | XY-shape pin check:Dec 04 16:39:55 2017 | XY-via check:May 03 10:28:12 2019 | check acute:May 03 10:18:08 2019 | check cline width:Jan 24 15:17:19 2019 | create plane:Apr 30 11:37:24 2019 | cross plane-BOTTOM-SGND3:May 03 10:22:39 2019 | cross plane-IN1-SGND1:May 03 10:19:57 2019 | cross plane-IN1-SGND:May 03 10:20:08 2019 | cross plane-IN2-SGND1:May 03 10:20:48 2019 | cross plane-IN2-SVCC:May 03 10:20:22 2019 | cross plane-IN3-SGND1:Aug 24 13:57:11 2017 | cross plane-IN3-SGND2:May 03 10:21:06 2019 | cross plane-IN3-SVCC1:May 03 10:21:20 2019 | cross plane-IN4-SGND2:May 03 10:22:15 2019 | cross plane-IN4-SGND3:May 03 10:21:47 2019 | cross plane-IN5-SGND3:Aug 24 13:58:47 2017 | cross plane-TOP-SGND:May 03 10:19:36 2019 | dxf to pin check:May 03 10:09:27 2019 | etch cross-IN1-IN2:Aug 24 13:54:39 2017 | etch cross-IN4-IN5:Aug 24 13:58:08 2017 | etch ref-BOTTOM-SGND3:May 03 10:23:10 2019 | etch ref-IN1-SGND1:May 03 10:20:08 2019 | etch ref-IN1-SGND:May 03 10:20:22 2019 | etch ref-IN2-SGND1:May 03 10:21:06 2019 | etch ref-IN2-SVCC:May 03 10:20:48 2019 | etch ref-IN3-SGND1:Aug 24 13:58:07 2017 | etch ref-IN3-SGND2:May 03 10:21:19 2019 | etch ref-IN3-SVCC1:May 03 10:21:46 2019 | etch ref-IN4-SGND2:May 03 10:22:39 2019 | etch ref-IN4-SGND3:May 03 10:22:14 2019 | etch ref-IN5-SGND3:Aug 24 13:59:26 2017 | etch ref-TOP-SGND:May 03 10:19:56 2019 | outline check:Apr 30 11:20:06 2019 | plane net check:May 03 10:11:41 2019 | prop check:May 03 10:19:06 2019 | shape min check:May 03 10:04:46 2019 | via check:May 03 10:28:12 2019 | DA0ZGEMBCC0 REV:C | FIGURE | TYPE | Circle | Oblong | SIZE | 8.0 | 10.0 | 12.0 | 14.0 | 18.0 | 22.0 | 32.0 | 59.0 | 118.0 | 130.0 | 138.0 | 146.0 | 220.0 | 24.0 | 30.0 | 38.0 | 43.0 | 47.0 | 63.0 | 67.0 | 102.0 | 158.0 | 51.0x24.0 | 67.0x39.0 | 75.0x24.0 | 79.0x28.0 | 83.0x31.0 | 114.0x102.0 | DRILL CHART: TOP to BOTTOM | ALL UNITS ARE IN MILS | PLATED | NON-PLATED | ROTATION | - | 90.000 | 0.000 | QTY | 3469 | 6958 | 71 | 1104 | 104 | 14 | 9 | 1 | 13 | 11804 | 19 | 52 | TOTAL HOLES: | VL | TBT | PCIe | PCIe/SATA | MODEL:ZGE | REV:C | DA0ZGEMBCC0 | K
